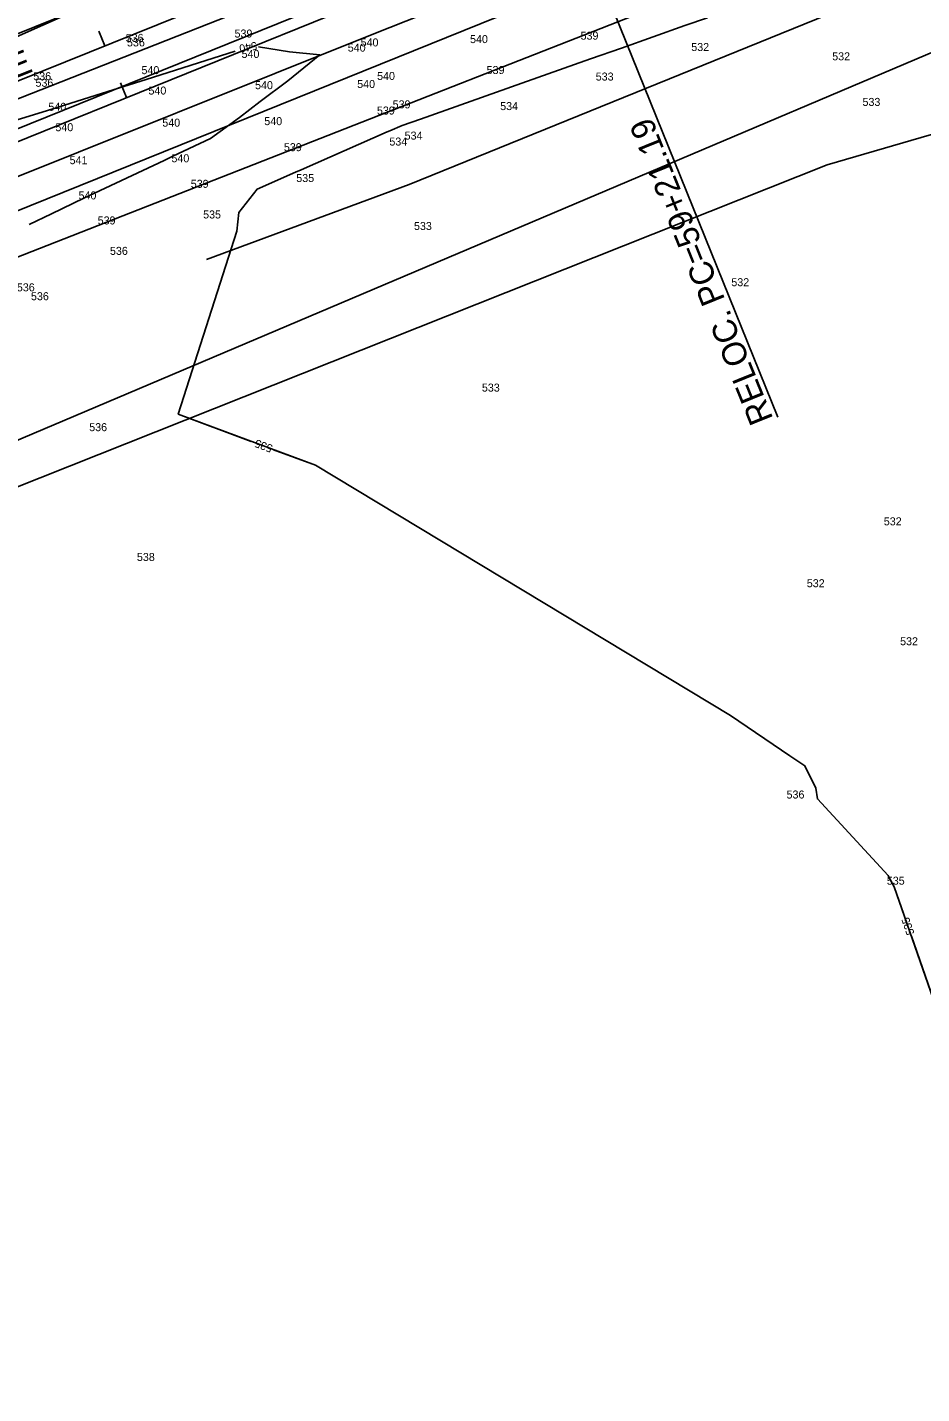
# Model space of a CAD drawing. Extents: x 1787461 to 1970323, y 938412 to 1118748.
# Drawn here: x 1967486.5 to 1967710, y 1117433.3 to 1117774.7 of the extents above; entities that cross this region are included whole.
import ezdxf

# ---------------------------------------------------------------- set-up
doc = ezdxf.new("R2010")
doc.units = 0
for name, color, linetype in [('Default', 7, 'Continuous'), ('HHA ADDITIONAL XSs', 7, 'Continuous'), ('Level 1', 7, 'Continuous'), ('RD_EX_DV_Prop', 7, 'Continuous'), ('RD_EX_Fence_Other', 7, 'Continuous'), ('RD_EX_Road', 7, 'Continuous'), ('RD_EX_VEG', 7, 'Continuous'), ('RD_HC_CL', 7, 'Continuous'), ('RD_HC_CL_Rel', 7, 'Continuous'), ('RD_HC_Data_Rel', 7, 'Continuous'), ('RD_HC_Data_Tic', 7, 'Continuous'), ('RD_HC_Data_Tic_Rel', 7, 'Continuous'), ('RD_PD_Final_TrvlWay', 7, 'Continuous')]:
    doc.layers.add(name, color=color, linetype=linetype)

msp = doc.modelspace()

# ---------------------------------------------------------------- linework, layer by layer
at = {"layer": 'Default'}
for points in [[(1967656.47, 1117777.08), (1967650.85, 1117775.1), (1967634.97, 1117769.49), (1967627.29, 1117766.79), (1967610.06, 1117760.7), (1967603.74, 1117758.49), (1967584.74, 1117751.76), (1967580.2, 1117750.17), (1967577.14, 1117748.82), (1967576.43, 1117748.53), (1967554.96, 1117739.06), (1967553.54, 1117738.47), (1967543.93, 1117734.19), (1967539.4, 1117728.42), (1967538.83, 1117723.7), (1967524.23, 1117678.01), (1967542.42, 1117671.22)], [(1967656.47, 1117777.08), (1967650.85, 1117775.1), (1967634.97, 1117769.49), (1967627.29, 1117766.79), (1967610.06, 1117760.7), (1967603.74, 1117758.49), (1967584.74, 1117751.76), (1967580.2, 1117750.17), (1967577.14, 1117748.82), (1967576.43, 1117748.53), (1967554.96, 1117739.06), (1967553.54, 1117738.47), (1967543.93, 1117734.19), (1967539.4, 1117728.42), (1967538.83, 1117723.7), (1967524.23, 1117678.01), (1967542.42, 1117671.22)], [(1967656.47, 1117777.08), (1967650.85, 1117775.1), (1967634.97, 1117769.49), (1967627.29, 1117766.79), (1967610.06, 1117760.7), (1967603.74, 1117758.49), (1967584.74, 1117751.76), (1967580.2, 1117750.17), (1967577.14, 1117748.82), (1967576.43, 1117748.53), (1967554.96, 1117739.06), (1967553.54, 1117738.47), (1967543.93, 1117734.19), (1967539.4, 1117728.42), (1967538.83, 1117723.7), (1967524.23, 1117678.01), (1967542.42, 1117671.22)], [(1967656.47, 1117777.08), (1967650.85, 1117775.1), (1967634.97, 1117769.49), (1967627.29, 1117766.79), (1967610.06, 1117760.7), (1967603.74, 1117758.49), (1967584.74, 1117751.76), (1967580.2, 1117750.17), (1967577.14, 1117748.82), (1967576.43, 1117748.53), (1967554.96, 1117739.06), (1967553.54, 1117738.47), (1967543.93, 1117734.19), (1967539.4, 1117728.42), (1967538.83, 1117723.7), (1967524.23, 1117678.01), (1967542.42, 1117671.22)], [(1967656.47, 1117777.08), (1967650.85, 1117775.1), (1967634.97, 1117769.49), (1967627.29, 1117766.79), (1967610.06, 1117760.7), (1967603.74, 1117758.49), (1967584.74, 1117751.76), (1967580.2, 1117750.17), (1967577.14, 1117748.82), (1967576.43, 1117748.53), (1967554.96, 1117739.06), (1967553.54, 1117738.47), (1967543.93, 1117734.19), (1967539.4, 1117728.42), (1967538.83, 1117723.7), (1967524.23, 1117678.01), (1967542.42, 1117671.22)], [(1967656.47, 1117777.08), (1967650.85, 1117775.1), (1967634.97, 1117769.49), (1967627.29, 1117766.79), (1967610.06, 1117760.7), (1967603.74, 1117758.49), (1967584.74, 1117751.76), (1967580.2, 1117750.17), (1967577.14, 1117748.82), (1967576.43, 1117748.53), (1967554.96, 1117739.06), (1967553.54, 1117738.47), (1967543.93, 1117734.19), (1967539.4, 1117728.42), (1967538.83, 1117723.7), (1967524.23, 1117678.01), (1967542.42, 1117671.22)], [(1967650.85, 1117775.1), (1967634.97, 1117769.49), (1967627.29, 1117766.79), (1967610.06, 1117760.7), (1967603.74, 1117758.49), (1967584.74, 1117751.76), (1967580.2, 1117750.17), (1967577.14, 1117748.82), (1967576.43, 1117748.53), (1967554.96, 1117739.06), (1967553.54, 1117738.47), (1967543.93, 1117734.19), (1967539.4, 1117728.42), (1967538.83, 1117723.7), (1967524.23, 1117678.01), (1967558.5, 1117665.23), (1967662.24, 1117602.69), (1967677.08, 1117592.62), (1967680.83, 1117590.15), (1967683.53, 1117584.56), (1967683.97, 1117581.86), (1967701.67, 1117562.72), (1967702.08, 1117561.94), (1967703.15, 1117559.88), (1967721.29, 1117507.74)], [(1967544.24, 1117769.82), (1967552, 1117768.54), (1967559.57, 1117767.76), (1967551.59, 1117761.32), (1967544.72, 1117756.17), (1967539.56, 1117752.14), (1967532.29, 1117746.86), (1967522.89, 1117742.46), (1967520.67, 1117741.4), (1967500.61, 1117731.96), (1967492.58, 1117728.06), (1967486.96, 1117725.41)], [(1967544.24, 1117769.82), (1967552, 1117768.54), (1967559.57, 1117767.76), (1967551.59, 1117761.32), (1967544.72, 1117756.17), (1967539.56, 1117752.14), (1967532.29, 1117746.86), (1967522.89, 1117742.46), (1967520.67, 1117741.4), (1967500.61, 1117731.96), (1967492.58, 1117728.06), (1967486.96, 1117725.41)], [(1967544.24, 1117769.82), (1967552, 1117768.54), (1967559.57, 1117767.76), (1967551.59, 1117761.32), (1967544.72, 1117756.17), (1967539.56, 1117752.14), (1967532.29, 1117746.86), (1967522.89, 1117742.46), (1967520.67, 1117741.4), (1967500.61, 1117731.96), (1967492.58, 1117728.06), (1967486.96, 1117725.41)], [(1967544.24, 1117769.82), (1967552, 1117768.54), (1967559.57, 1117767.76), (1967551.59, 1117761.32), (1967544.72, 1117756.17), (1967539.56, 1117752.14), (1967532.29, 1117746.86), (1967522.89, 1117742.46), (1967520.67, 1117741.4), (1967500.61, 1117731.96), (1967492.58, 1117728.06), (1967486.96, 1117725.41)], [(1967544.24, 1117769.82), (1967552, 1117768.54), (1967559.57, 1117767.76), (1967551.59, 1117761.32), (1967544.72, 1117756.17), (1967539.56, 1117752.14), (1967532.29, 1117746.86), (1967522.89, 1117742.46), (1967520.67, 1117741.4), (1967500.61, 1117731.96), (1967492.58, 1117728.06), (1967486.96, 1117725.41)], [(1967544.24, 1117769.82), (1967552, 1117768.54), (1967559.57, 1117767.76), (1967551.59, 1117761.32), (1967544.72, 1117756.17), (1967539.56, 1117752.14), (1967532.29, 1117746.86), (1967522.89, 1117742.46), (1967520.67, 1117741.4), (1967500.61, 1117731.96), (1967492.58, 1117728.06), (1967486.96, 1117725.41)], [(1967544.24, 1117769.82), (1967552, 1117768.54), (1967559.57, 1117767.76), (1967551.59, 1117761.32), (1967544.72, 1117756.17), (1967539.56, 1117752.14), (1967532.29, 1117746.86), (1967522.89, 1117742.46), (1967520.67, 1117741.4), (1967500.61, 1117731.96), (1967492.58, 1117728.06), (1967486.96, 1117725.41)], [(1967443.31, 1117738.03), (1967461.28, 1117744.21), (1967462.61, 1117744.65), (1967462.8, 1117744.72), (1967468.49, 1117746.69), (1967468.6, 1117746.73), (1967470.34, 1117747.38), (1967492.34, 1117754.16), (1967503.68, 1117757.74), (1967516.18, 1117761.63), (1967538.47, 1117768.72)], [(1967443.31, 1117738.03), (1967461.28, 1117744.21), (1967462.61, 1117744.65), (1967462.8, 1117744.72), (1967468.49, 1117746.69), (1967468.6, 1117746.73), (1967470.34, 1117747.38), (1967492.34, 1117754.16), (1967503.68, 1117757.74), (1967516.18, 1117761.63), (1967538.47, 1117768.72)], [(1967443.31, 1117738.03), (1967461.28, 1117744.21), (1967462.61, 1117744.65), (1967462.8, 1117744.72), (1967468.49, 1117746.69), (1967468.6, 1117746.73), (1967470.34, 1117747.38), (1967492.34, 1117754.16), (1967503.68, 1117757.74), (1967516.18, 1117761.63), (1967538.47, 1117768.72)], [(1967443.31, 1117738.03), (1967461.28, 1117744.21), (1967462.61, 1117744.65), (1967462.8, 1117744.72), (1967468.49, 1117746.69), (1967468.6, 1117746.73), (1967470.34, 1117747.38), (1967492.34, 1117754.16), (1967503.68, 1117757.74), (1967516.18, 1117761.63), (1967538.47, 1117768.72)], [(1967443.31, 1117738.03), (1967461.28, 1117744.21), (1967462.61, 1117744.65), (1967462.8, 1117744.72), (1967468.49, 1117746.69), (1967468.6, 1117746.73), (1967470.34, 1117747.38), (1967492.34, 1117754.16), (1967503.68, 1117757.74), (1967516.18, 1117761.63), (1967538.47, 1117768.72)], [(1967443.31, 1117738.03), (1967461.28, 1117744.21), (1967462.61, 1117744.65), (1967462.8, 1117744.72), (1967468.49, 1117746.69), (1967468.6, 1117746.73), (1967470.34, 1117747.38), (1967492.34, 1117754.16), (1967503.68, 1117757.74), (1967516.18, 1117761.63), (1967538.47, 1117768.72)], [(1967443.31, 1117738.03), (1967461.28, 1117744.21), (1967462.61, 1117744.65), (1967462.8, 1117744.72), (1967468.49, 1117746.69), (1967468.6, 1117746.73), (1967470.34, 1117747.38), (1967492.34, 1117754.16), (1967503.68, 1117757.74), (1967516.18, 1117761.63), (1967538.47, 1117768.72)], [(1967548.05, 1117669.13), (1967558.5, 1117665.23), (1967662.24, 1117602.69), (1967677.08, 1117592.62), (1967680.83, 1117590.15), (1967683.53, 1117584.56), (1967683.97, 1117581.86), (1967701.67, 1117562.72), (1967702.08, 1117561.94), (1967703.15, 1117559.88), (1967705.47, 1117553.2)], [(1967548.05, 1117669.13), (1967558.5, 1117665.23), (1967662.24, 1117602.69), (1967677.08, 1117592.62), (1967680.83, 1117590.15), (1967683.53, 1117584.56), (1967683.97, 1117581.86), (1967701.67, 1117562.72), (1967702.08, 1117561.94), (1967703.15, 1117559.88), (1967705.47, 1117553.2)], [(1967548.05, 1117669.13), (1967558.5, 1117665.23), (1967662.24, 1117602.69), (1967677.08, 1117592.62), (1967680.83, 1117590.15), (1967683.53, 1117584.56), (1967683.97, 1117581.86), (1967701.67, 1117562.72), (1967702.08, 1117561.94), (1967703.15, 1117559.88), (1967705.47, 1117553.2)], [(1967548.05, 1117669.13), (1967558.5, 1117665.23), (1967662.24, 1117602.69), (1967677.08, 1117592.62), (1967680.83, 1117590.15), (1967683.53, 1117584.56), (1967683.97, 1117581.86), (1967701.67, 1117562.72), (1967702.08, 1117561.94), (1967703.15, 1117559.88), (1967705.47, 1117553.2)], [(1967548.05, 1117669.13), (1967558.5, 1117665.23), (1967662.24, 1117602.69), (1967677.08, 1117592.62), (1967680.83, 1117590.15), (1967683.53, 1117584.56), (1967683.97, 1117581.86), (1967701.67, 1117562.72), (1967702.08, 1117561.94), (1967703.15, 1117559.88), (1967705.47, 1117553.2)], [(1967548.05, 1117669.13), (1967558.5, 1117665.23), (1967662.24, 1117602.69), (1967677.08, 1117592.62), (1967680.83, 1117590.15), (1967683.53, 1117584.56), (1967683.97, 1117581.86), (1967701.67, 1117562.72), (1967702.08, 1117561.94), (1967703.15, 1117559.88), (1967705.47, 1117553.2)], [(1967707.45, 1117547.54), (1967721.29, 1117507.74), (1967726.43, 1117513.31), (1967726.84, 1117512.62), (1967730.47, 1117509.37), (1967733.85, 1117499.01), (1967748.51, 1117494.25), (1967757.67, 1117474.76), (1967774.54, 1117468.91), (1967770.4, 1117473.79), (1967775.91, 1117468.26), (1967776.03, 1117468.19), (1967777.26, 1117467.38), (1967791.69, 1117452.17), (1967799.51, 1117440.56), (1967803.01, 1117436.4), (1967803.55, 1117436.04), (1967803.99, 1117435.25), (1967807.61, 1117433.26)], [(1967707.45, 1117547.54), (1967721.29, 1117507.74), (1967726.43, 1117513.31), (1967726.84, 1117512.62), (1967730.47, 1117509.37), (1967733.85, 1117499.01), (1967748.51, 1117494.25), (1967757.67, 1117474.76), (1967774.54, 1117468.91), (1967770.4, 1117473.79), (1967775.91, 1117468.26), (1967776.03, 1117468.19), (1967777.26, 1117467.38), (1967791.69, 1117452.17), (1967799.51, 1117440.56), (1967803.01, 1117436.4), (1967803.55, 1117436.04), (1967803.99, 1117435.25), (1967807.61, 1117433.26)], [(1967707.45, 1117547.54), (1967721.29, 1117507.74), (1967726.43, 1117513.31), (1967726.84, 1117512.62), (1967730.47, 1117509.37), (1967733.85, 1117499.01), (1967748.51, 1117494.25), (1967757.67, 1117474.76), (1967774.54, 1117468.91), (1967770.4, 1117473.79), (1967775.91, 1117468.26), (1967776.03, 1117468.19), (1967777.26, 1117467.38), (1967791.69, 1117452.17), (1967799.51, 1117440.56), (1967803.01, 1117436.4), (1967803.55, 1117436.04), (1967803.99, 1117435.25), (1967807.61, 1117433.26)], [(1967707.45, 1117547.54), (1967721.29, 1117507.74), (1967726.43, 1117513.31), (1967726.84, 1117512.62), (1967730.47, 1117509.37), (1967733.85, 1117499.01), (1967748.51, 1117494.25), (1967757.67, 1117474.76), (1967774.54, 1117468.91), (1967770.4, 1117473.79), (1967775.91, 1117468.26), (1967776.03, 1117468.19), (1967777.26, 1117467.38), (1967791.69, 1117452.17), (1967799.51, 1117440.56), (1967803.01, 1117436.4), (1967803.55, 1117436.04), (1967803.99, 1117435.25), (1967807.61, 1117433.26)], [(1967707.45, 1117547.54), (1967721.29, 1117507.74), (1967726.43, 1117513.31), (1967726.84, 1117512.62), (1967730.47, 1117509.37), (1967733.85, 1117499.01), (1967748.51, 1117494.25), (1967757.67, 1117474.76), (1967774.54, 1117468.91), (1967770.4, 1117473.79), (1967775.91, 1117468.26), (1967776.03, 1117468.19), (1967777.26, 1117467.38), (1967791.69, 1117452.17), (1967799.51, 1117440.56), (1967803.01, 1117436.4), (1967803.55, 1117436.04), (1967803.99, 1117435.25), (1967807.61, 1117433.26)], [(1967707.45, 1117547.54), (1967721.29, 1117507.74), (1967726.43, 1117513.31), (1967726.84, 1117512.62), (1967730.47, 1117509.37), (1967733.85, 1117499.01), (1967748.51, 1117494.25), (1967757.67, 1117474.76), (1967774.54, 1117468.91), (1967770.4, 1117473.79), (1967775.91, 1117468.26), (1967776.03, 1117468.19), (1967777.26, 1117467.38), (1967791.69, 1117452.17), (1967799.51, 1117440.56), (1967803.01, 1117436.4), (1967803.55, 1117436.04), (1967803.99, 1117435.25), (1967807.61, 1117433.26)]]:
    msp.add_lwpolyline(points, dxfattribs=at)
at = {"layer": 'HHA ADDITIONAL XSs'}
msp.add_line((1967378.44, 1117686.19), (1967629.45, 1117787.58), dxfattribs=at)
msp.add_lwpolyline([(1969308.89, 1117819.66), (1967912.94, 1117853.44), (1967442.55, 1117653.93), (1967107.32, 1117508.48)], dxfattribs=at)
at = {"layer": 'Level 1'}
msp.add_lwpolyline([(1968654.57, 1117840.68), (1968058.24, 1117848.48), (1967686.38, 1117740.3), (1966964.76, 1117453.35)], dxfattribs=at)
at = {"layer": 'RD_EX_DV_Prop'}
msp.add_line((1966769.51, 1117457.48), (1967696.84, 1117832.06), dxfattribs=at)
at = {"layer": 'RD_EX_Fence_Other'}
msp.add_lwpolyline([(1967531.32, 1117716.68), (1967581.91, 1117735.39), (1967686.43, 1117777.78)], dxfattribs=at)
at = {"layer": 'RD_EX_Road'}
for points in [[(1966768.28, 1117466.83), (1966868.93, 1117506.7), (1966969.96, 1117548.31), (1967069.86, 1117589.6), (1967171.37, 1117630.89), (1967269.56, 1117671.02), (1967319.89, 1117691.93), (1967370.29, 1117712.23), (1967469.03, 1117750.91), (1967565.44, 1117788.86), (1967660.02, 1117826.88), (1967693.17, 1117840.55), (1967696.66, 1117832.16)], [(1967338.81, 1117679.22), (1967378.03, 1117695.56), (1967474.86, 1117733.75), (1967572.69, 1117772.86), (1967666.47, 1117810.1), (1967700.41, 1117823.36), (1967696.66, 1117832.16)]]:
    msp.add_lwpolyline(points, dxfattribs=at)
at = {"layer": 'RD_EX_VEG'}
for points in [[(1967420.8, 1117819.08), (1967452.15, 1117758.28), (1967558.57, 1117805.53), (1967843.24, 1117926.43), (1967916.63, 1117956.61), (1968008.44, 1117968.2), (1968060.25, 1117967.44), (1968104.58, 1117972.69), (1968157.63, 1117966.15), (1968211.15, 1117963.44), (1968421.93, 1117955.99), (1968535.19, 1117951.62)], [(1967302.31, 1117610.37), (1967337.76, 1117649.58), (1967352.05, 1117663.92), (1967393.53, 1117676.59), (1967483.38, 1117717.02), (1967710.35, 1117806.03), (1967888.86, 1117873.57), (1967928.06, 1117882.04), (1967957.92, 1117887.35), (1967975.7, 1117893.86), (1968013.09, 1117903.71), (1968102.91, 1117899.22), (1968154.08, 1117904.84), (1968208.62, 1117905.24), (1968319.32, 1117902.87), (1968421.81, 1117901.58), (1968527.92, 1117886.31)]]:
    msp.add_lwpolyline(points, dxfattribs=at)
at = {"layer": 'RD_HC_CL'}
msp.add_line((1966769.51, 1117457.48), (1967848.24, 1117893.22), dxfattribs=at)
at = {"layer": 'RD_HC_CL_Rel'}
msp.add_line((1967367.21, 1117714.01), (1967618.21, 1117815.4), dxfattribs=at)
at = {"layer": 'RD_HC_Data_Rel'}
msp.add_line((1967618.21, 1117815.4), (1967674.03, 1117677.23), dxfattribs=at)
at = {"layer": 'RD_HC_Data_Tic'}
msp.add_line((1967511.28, 1117757.11), (1967509.78, 1117760.82), dxfattribs=at)
at = {"layer": 'RD_HC_Data_Tic_Rel'}
msp.add_line((1967505.85, 1117770.01), (1967504.35, 1117773.72), dxfattribs=at)
at = {"layer": 'RD_PD_Final_TrvlWay'}
for p, q in [((1967363.09, 1117724.21), (1967614.09, 1117825.6)), ((1967371.33, 1117703.81), (1967622.33, 1117805.2))]:
    msp.add_line(p, q, dxfattribs=at)

# ---------------------------------------------------------------- texts
at = {"layer": 'Default'}
for s, p in [('536', (1967511.09, 1117771.03)), ('539', (1967538.29, 1117772.12)), ('540', (1967597.15, 1117770.73)), ('539', (1967624.77, 1117771.59)), ('536', (1967511.41, 1117769.9)), ('540', (1967540.04, 1117767.02)), ('540', (1967566.59, 1117768.6)), ('540', (1967569.8, 1117769.9)), ('532', (1967652.44, 1117768.75)), ('532', (1967687.66, 1117766.42)), ('536', (1967488, 1117761.45)), ('540', (1967515.03, 1117762.97)), ('540', (1967573.92, 1117761.51)), ('539', (1967601.29, 1117763)), ('533', (1967628.56, 1117761.37)), ('536', (1967488.54, 1117759.82)), ('540', (1967516.78, 1117757.87)), ('540', (1967543.42, 1117759.22)), ('540', (1967568.94, 1117759.51)), ('540', (1967491.77, 1117753.81)), ('539', (1967577.81, 1117754.42)), ('534', (1967604.68, 1117753.99)), ('533', (1967695.23, 1117755.03)), ('540', (1967520.24, 1117749.85)), ('540', (1967545.73, 1117750.23)), ('539', (1967573.88, 1117752.87)), ('540', (1967493.52, 1117748.71)), ('534', (1967580.8, 1117746.62)), ('539', (1967550.62, 1117743.72)), ('534', (1967576.99, 1117745.13)), ('541', (1967497.07, 1117740.47)), ('540', (1967522.52, 1117740.95)), ('539', (1967527.35, 1117734.57)), ('535', (1967553.72, 1117736.02)), ('540', (1967499.3, 1117731.67)), ('535', (1967530.44, 1117726.91)), ('539', (1967504.09, 1117725.42)), ('533', (1967583.14, 1117724.03)), ('536', (1967507.16, 1117717.81)), ('532', (1967662.45, 1117709.98)), ('536', (1967483.89, 1117708.7)), ('536', (1967487.42, 1117706.48)), ('533', (1967600.11, 1117683.65)), ('536', (1967501.97, 1117673.76)), ('532', (1967700.55, 1117650.23)), ('538', (1967513.9, 1117641.33)), ('532', (1967681.31, 1117634.77)), ('532', (1967704.63, 1117620.27)), ('536', (1967676.25, 1117581.97)), ('535', (1967701.31, 1117560.44))]:
    msp.add_text(s, height=2, dxfattribs=at).set_placement(p)
for s, rotation, p in [('540', 190.7856, (1967543.71, 1117771.1)), ('540', 190.7856, (1967543.71, 1117771.1)), ('540', 190.7856, (1967543.71, 1117771.1)), ('540', 190.7856, (1967543.71, 1117771.1)), ('540', 190.7856, (1967543.71, 1117771.1)), ('540', 190.7856, (1967543.71, 1117771.1)), ('540', 190.7856, (1967543.71, 1117771.1)), ('535', 159.555, (1967548, 1117670.21)), ('535', 159.555, (1967548, 1117670.21)), ('535', 159.555, (1967548, 1117670.21)), ('535', 159.555, (1967548, 1117670.21)), ('535', 159.555, (1967548, 1117670.21)), ('535', 159.555, (1967548, 1117670.21)), ('535', 109.1818, (1967708.25, 1117548.27)), ('535', 109.1818, (1967708.25, 1117548.27)), ('535', 109.1818, (1967708.25, 1117548.27)), ('535', 109.1818, (1967708.25, 1117548.27)), ('535', 109.1818, (1967708.25, 1117548.27)), ('535', 109.1818, (1967708.25, 1117548.27))]:
    msp.add_text(s, height=2, rotation=rotation, dxfattribs=at).set_placement(p)
at = {"layer": 'RD_HC_Data_Rel'}
for s, rotation, p in [('N 68%%d 00\' 15" E', 21.9958, (1967437.71, 1117743.35)), ('RELOC. PC=59+21.19', 111.9958, (1967672.99, 1117676.87))]:
    msp.add_text(s, height=6, rotation=rotation, dxfattribs=at).set_placement(p)

doc.saveas('drawing.dxf')
